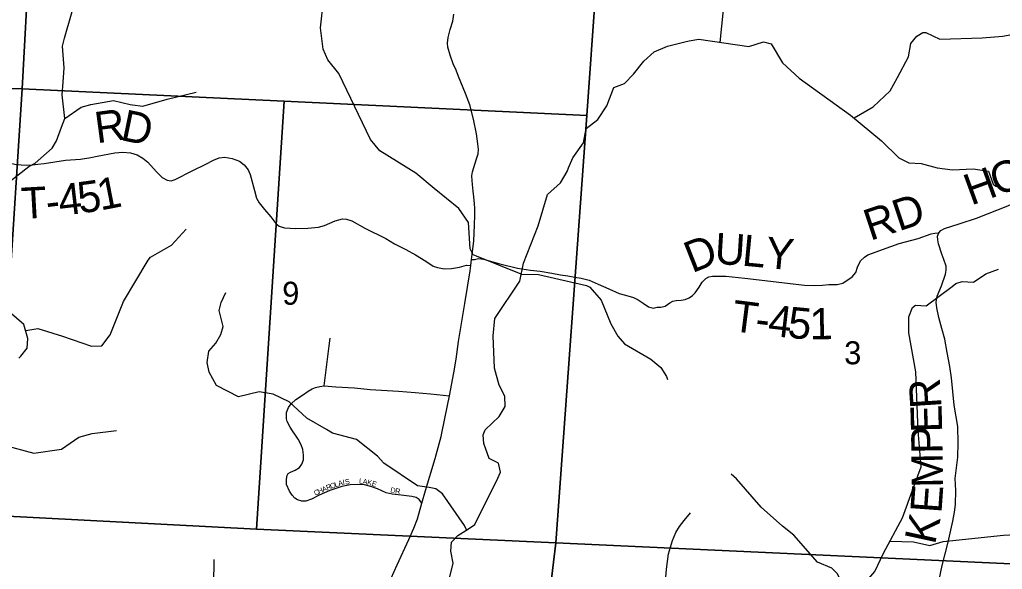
# Model space of a CAD drawing. Extents: x 1878108 to 2183446, y 146837 to 508383.
# Drawn here: x 2036927 to 2046360, y 319271 to 324551 of the extents above; entities that cross this region are included whole.
import ezdxf

# ---------------------------------------------------------------- set-up
doc = ezdxf.new("R2010")
doc.units = 0
for name, color, linetype in [('GM_X_County_Road', 7, 'Continuous'), ('GM_X_County_Road_Text', 7, 'Continuous'), ('GM_X_Minor_River', 7, 'Continuous'), ('GM_X_Section', 7, 'Continuous'), ('GM_X_Section_Text', 7, 'Continuous'), ('GM_X_Township_Road', 7, 'Continuous'), ('GM_X_Township_Road_Text', 7, 'Continuous'), ('GM_X_Township_Subdivision', 7, 'Continuous'), ('GM_X_Township_Subdivision_Text', 7, 'Continuous')]:
    doc.layers.add(name, color=color, linetype=linetype)

msp = doc.modelspace()

# ---------------------------------------------------------------- linework, layer by layer
at = {"layer": 'GM_X_County_Road'}
for points in [[(2041269.8, 322297.9), (2041284.9, 322422.1), (2041293.9, 322578.5), (2041296.1, 322669), (2041296.1, 322736.1), (2041291.9, 322782.5), (2041287.2, 322850.1), (2041280.5, 322903.8), (2041273.8, 322967.5), (2041270.4, 323006.6), (2041268.2, 323049), (2041273.8, 323090.4), (2041284.9, 323131.7), (2041312.9, 323213.3), (2041327.4, 323261.4), (2041330.8, 323306.1), (2041324, 323356.4), (2041310.6, 323452.5), (2041283.8, 323595.6), (2041246.9, 323733), (2041205.6, 323840.3), (2041140.8, 324003.5), (2041116.2, 324065), (2041089.3, 324126.4), (2041058, 324208), (2041036.8, 324287.4), (2041033.5, 324324.3), (2041039, 324377.9), (2041059.2, 324456.1), (2041084.9, 324535.5), (2041094.9, 324603.7)], [(2046142, 322656.2), (2046379.4, 322750), (2046479.7, 322791.1), (2046660.9, 322855.4), (2047032.3, 322992.9), (2047151.9, 323036.6), (2047223.9, 323075.2), (2047316.4, 323151), (2047355.3, 323178.6), (2047429.5, 323215.3), (2047478.4, 323255.1), (2047541.3, 323334.8), (2047615.9, 323427.3), (2047677.6, 323510.9), (2047707.1, 323558.4), (2047747, 323635.6), (2047755, 323655.9)], [(2045752.9, 319171.1), (2045782.1, 319307.1), (2045838.1, 319530.9), (2045885.1, 319733), (2045901.6, 319819.5), (2045910.5, 319893.2), (2045911.8, 320029.2), (2045907.9, 320142.3), (2045930.9, 320349.6), (2045936, 320481.8), (2045932.1, 320644.5), (2045897.8, 320848), (2045871.1, 321111.1), (2045854.6, 321217.9), (2045830.4, 321353.9), (2045807.6, 321481.1), (2045778.3, 321582.8), (2045750.3, 321689.6), (2045731.3, 321783.6), (2045724.9, 321838.3), (2045732.5, 321894.2), (2045774.5, 321994.7), (2045812.6, 322107.3), (2045819, 322143.3), (2045819, 322181.9), (2045797.2, 322246.1), (2045777.9, 322297.5), (2045745.7, 322396.5), (2045739.3, 322435.1), (2045736.7, 322469.8), (2045749.6, 322504.5), (2045770.2, 322526.3), (2045804.9, 322544.3), (2045946.2, 322588), (2046122.3, 322648.4), (2046142, 322656.2)], [(2041250.2, 322138.1), (2041258.7, 322190.3), (2041263.5, 322246.1), (2041269.8, 322297.9)], [(2040436.7, 319059.3), (2040551.8, 319315.4), (2040661.1, 319556.4), (2040712, 319665.5), (2040744.7, 319756.4), (2040787.1, 319905.5), (2040821.1, 320026.7), (2040914.4, 320337), (2040971.4, 320545.5), (2041012.6, 320735.8), (2041052.6, 320938.2), (2041093.8, 321157.6), (2041115.6, 321289.7), (2041139.9, 321458.2), (2041199.3, 321824.3), (2041250.2, 322138.1)]]:
    msp.add_lwpolyline(points, dxfattribs=at)
at = {"layer": 'GM_X_Minor_River'}
for points in [[(2043652.3, 324332.3), (2043682.3, 324645.8), (2043736.7, 324719.9), (2043869.4, 324819.7), (2043901.6, 324871.7), (2044019.1, 325184.5), (2044045.3, 325212.5), (2044131.5, 325222.1), (2044157.7, 325254.1), (2044230, 325316.1), (2044387.2, 325532.2), (2044552, 325654), (2044652.7, 325780.1), (2044719.1, 325844), (2044834.1, 326054.4), (2044902.6, 326140.4), (2044989.6, 326334.8), (2045007.8, 326374.9), (2045034.2, 326463.1), (2045030.7, 326579.6), (2044897.9, 326939.7), (2044840.8, 327154.9), (2044827.5, 327325.6)], [(2037361.7, 323602.4), (2037335.1, 323828.4), (2037345, 323950.6), (2037352.8, 324086.8), (2037338.6, 324297.1), (2037358.5, 324371.2), (2037485.8, 324820.1), (2037541.6, 324932.3), (2037709.4, 325024.8), (2037841.1, 325125.1), (2038039.1, 325301.9)], [(2041741.6, 322105.7), (2041310.5, 322278.9), (2041278.5, 322291.1), (2041252.7, 322349.4), (2041235.7, 322602.6), (2041142.1, 322737.5), (2040906.6, 322929.4), (2040730.9, 323076.8), (2040385.2, 323289.2), (2040295.5, 323400.1), (2039989.7, 324032.1), (2039886.1, 324165.1), (2039840.4, 324265.7), (2039813.3, 324472.7), (2039842.4, 324733.6)], [(2044936, 323607.8), (2045120.7, 323713.4), (2045281.7, 323867.3), (2045352.3, 323993.5), (2045459.3, 324191.8), (2045479.9, 324320.3), (2045538.3, 324392.3), (2045596.5, 324426.2), (2045626.6, 324426), (2045760.5, 324363.2), (2046167.3, 324377.4), (2046363.6, 324390.5), (2046646.3, 324445.5), (2046744.6, 324483.2), (2046835, 324533)], [(2041057.1, 319199.4), (2041087.7, 319329.8), (2041066.2, 319444.3), (2041072.5, 319532.7), (2041132.9, 319594.7), (2041235.3, 319660.5), (2041297.6, 319702.3), (2041517.9, 320147.2), (2041542.1, 320205.3), (2041524.5, 320291.7), (2041432.5, 320334.3), (2041381, 320481.2), (2041377.4, 320563.5), (2041393.6, 320609.6), (2041530.4, 320739.6), (2041586.9, 320833.7), (2041585.3, 320934.1), (2041529.6, 321038.8), (2041484.2, 321203.7), (2041473.5, 321513), (2041488.3, 321679.6), (2041728.2, 322040), (2041762.9, 322210.5), (2041902.7, 322571.4), (2041992.1, 322872.2), (2042116.8, 322982.1), (2042181.3, 323092.3), (2042195.5, 323128.3), (2042238, 323224.5), (2042338.7, 323366.7), (2042363.4, 323505.1), (2042477.9, 323593), (2042564.6, 323723.1), (2042631.5, 323897.5), (2042731.8, 323937.2), (2042818.3, 324027.2), (2042917, 324151.3), (2043017.5, 324241.2), (2043146, 324294.8), (2043310.4, 324338.2), (2043352.5, 324346.1), (2043446.7, 324361.7), (2043925.2, 324293.2), (2044067.7, 324338.8), (2044141.7, 324318.4), (2044249.1, 324137.1), (2044410.7, 323989.8), (2044902, 323632.1), (2045199.5, 323387.7), (2045365.1, 323224.3), (2045463, 323175.6), (2045581.2, 323169.1), (2045733.3, 323126.2), (2045881.5, 323109.5), (2046079.8, 323118.6), (2046226, 323093.8), (2046271.5, 322969.1), (2046297.5, 322950.9), (2046475.5, 322897.9)], [(2036766.7, 322944.1), (2037014.2, 323138.9), (2037076.1, 323171), (2037237.8, 323317.5), (2037281.7, 323385.7), (2037327.5, 323518), (2037361.3, 323602.1), (2037517.1, 323708.6), (2037608.9, 323734.8), (2037826.7, 323773.2), (2037986.5, 323735.5), (2038008.5, 323731.5), (2038108.4, 323719.7), (2038344.1, 323788.2), (2038621.7, 323852.8)], [(2036986.1, 321564.6), (2037101.9, 321584.9), (2037337.7, 321511.2), (2037617.6, 321413.6), (2037715.5, 321417.8), (2037795.3, 321522), (2037924.8, 321842.7), (2038160.1, 322241.7), (2038184, 322269.8), (2038385.7, 322384.3), (2038525.3, 322538.8)], [(2044903.5, 318935), (2044954.6, 318982.7), (2044999.1, 319089), (2045136, 319251), (2045218.9, 319425.3), (2045400.6, 319765.9), (2045508, 320056.6), (2045581, 320255.1), (2045552.4, 320602.7), (2045528.7, 321167.1), (2045462.2, 321542.9), (2045460.8, 321695.6), (2045497.3, 321785.8), (2045527.4, 321807.7), (2045627.5, 321803.2), (2045876.7, 321988.9), (2045912.9, 322016.8), (2045975.1, 322034.6), (2046081.2, 322030.1), (2046201.8, 322109.9), (2046324.2, 322153.5)], [(2041741.5, 322105.6), (2041906.7, 322101.4), (2042367, 321996.9), (2042399, 321982.7), (2042508.7, 321855.7), (2042599.9, 321628.3), (2042669.5, 321509.5), (2042733.3, 321436.9), (2042985.1, 321291.2), (2043082.9, 321208.4), (2043136.6, 321123.8), (2043144.5, 321093.6)], [(2039684.1, 320721.4), (2039512.2, 320880.3), (2039360.3, 320952.1), (2039224.4, 320975.9), (2039028.6, 320927.5), (2038814.8, 321035.2), (2038746.7, 321165.3), (2038726.6, 321257.4), (2038742.5, 321365.6), (2038810.3, 321441.8), (2038858.1, 321526), (2038880, 321602.1), (2038841.9, 321758.3), (2038859.8, 321832.4), (2038905.6, 321930.6)], [(2036918.4, 321298.1), (2036938.4, 321318.2), (2036998.2, 321394.4), (2037006.1, 321486.6), (2036968, 321622.7), (2036826, 321744.6)], [(2041214.5, 319650.1), (2041195.4, 319692.8), (2040984.4, 319997), (2040922.4, 320043.5), (2040856.4, 320057.8), (2040744.3, 320072.4), (2040422.7, 320290.8), (2040360.8, 320357.3), (2040159.2, 320518.9), (2039929.1, 320580.2), (2039871.1, 320612.6), (2039683.3, 320721.9)], [(2036407.8, 320580.2), (2036776.9, 320462.1), (2037063.5, 320386.5), (2037327.8, 320425.2), (2037495.8, 320540), (2037623.9, 320574.4), (2037856.2, 320605.1)], [(2045281.3, 319542.2), (2045505.8, 319534.5), (2045663.9, 319501.6), (2045792.3, 319537.2), (2046371.5, 319598.8), (2046545.8, 319608), (2046660.1, 319627.6), (2046718.4, 319671.5), (2046730.7, 319737.7), (2046715.1, 319852.3), (2046701.5, 319954.8), (2046710, 320057.1), (2046823.3, 320321.7), (2046837.7, 320416), (2046834, 320486.3)], [(2044943.9, 318818.1), (2044864.7, 319047.4), (2044777.3, 319228.5), (2044721.5, 319283), (2044585.5, 319339.9), (2044358.2, 319598), (2044248.4, 319684.8), (2044044.8, 319868.5), (2043807.6, 320140.7), (2043755.7, 320185.1)], [(2038790.7, 319364.9), (2038786.9, 319126.5), (2038807, 319070.5), (2038853.1, 318966.4), (2038981, 318817.8)]]:
    msp.add_lwpolyline(points, dxfattribs=at)
at = {"layer": 'GM_X_Section'}
for points in [[(2036950.3, 323885.9), (2036627, 323893.3), (2036446.5, 321096.2), (2033640.2, 321275.3), (2033930.4, 325304), (2037017.7, 325125.7)], [(2037017.7, 325125.7), (2042458, 324849.1), (2042369.9, 323629.5), (2039466.2, 323766.9), (2036950.3, 323885.9)], [(2042458, 324849.1), (2042459.2, 324865.4), (2047851.5, 324568.1), (2047485.7, 319275.5), (2042073.5, 319526.8), (2042369.9, 323629.5)], [(2036950.3, 323885.9), (2036684.8, 319786.8), (2036363.4, 319807.6), (2036446.5, 321096.2), (2036627, 323893.3)], [(2039466.2, 323766.9), (2039201.1, 319655.3), (2036684.8, 319786.8), (2036950.3, 323885.9)], [(2042369.9, 323629.5), (2042073.5, 319526.8), (2039201.1, 319655.3), (2039466.2, 323766.9)], [(2039201.1, 319655.3), (2042073.5, 319526.8), (2041944.4, 318463.8), (2041709.1, 314235.9), (2036314.8, 314510.5), (2036455.6, 316598.4), (2036600.2, 318782.6), (2036684.8, 319786.8)], [(2047485.7, 319275.5), (2047167.4, 313959), (2041709.1, 314235.9), (2041944.4, 318463.8), (2042073.5, 319526.8)]]:
    msp.add_lwpolyline(points, close=True, dxfattribs=at)
at = {"layer": 'GM_X_Township_Road'}
for points in [[(2035221.6, 323292.9), (2035423.7, 323292.9), (2035721.8, 323286.1), (2035830.9, 323271.5), (2036124.9, 323239.9), (2036573.9, 323218.2), (2036686.6, 323203.7), (2036782.4, 323184.3), (2036879.3, 323163.7), (2036942.4, 323155.2), (2037024.8, 323154), (2037101.4, 323162.8)], [(2037101.4, 323162.8), (2037161.8, 323169.7), (2037366.6, 323200), (2037510.8, 323210.9), (2037611.2, 323225.8), (2037672, 323240), (2037841.7, 323272.7), (2037918.1, 323277.6), (2037990.8, 323271.5), (2038053.9, 323253.3), (2038109.6, 323220.6), (2038156.9, 323180.6), (2038241.7, 323088.5), (2038295.1, 323034), (2038341.1, 323009.7), (2038381.1, 323003.7), (2038419.9, 323015.8), (2038583.5, 323097), (2038714.5, 323163.7), (2038788.4, 323201.2), (2038841.7, 323223), (2038897.5, 323230.3), (2038967.8, 323217), (2039036.9, 323190.3), (2039081.7, 323155.2), (2039119.3, 323107.9), (2039138.7, 323064.3), (2039182.3, 322909.1), (2039201.7, 322836.4), (2039224.7, 322791.5), (2039278.1, 322726.1), (2039337.5, 322657), (2039387.2, 322594), (2039416.3, 322568.5), (2039468.4, 322550.3), (2039576.3, 322543.1), (2039693.8, 322547.9), (2039794.4, 322558.8), (2039853.1, 322574.8), (2039954.4, 322618.2), (2040025.9, 322637.6), (2040063.5, 322634), (2040116.9, 322618.2), (2040239.3, 322549.1), (2040441.7, 322447.3), (2040524.1, 322396.4), (2040633.2, 322341.8), (2040726.5, 322292.2), (2040825.9, 322230.3), (2040895, 322181.9), (2040936.2, 322169.7), (2041000.5, 322158.8), (2041070.8, 322161.2), (2041148.4, 322172.2), (2041215, 322191.5), (2041258.7, 322190.3)], [(2041263.5, 322246.1), (2041293.4, 322247.4), (2041331.9, 322256.4), (2041378.2, 322248.7), (2041536.3, 322203.7), (2041704.7, 322165.1), (2041830.6, 322145.9), (2041921.9, 322134.3), (2042033.7, 322116.3), (2042117.3, 322099.6), (2042189.2, 322089.3), (2042254.8, 322077.7), (2042315.2, 322066.2), (2042393.6, 322046.9), (2042478.4, 322010.9), (2042583.8, 321964.6), (2042681.5, 321920.9), (2042743.2, 321905.5), (2042819.1, 321882.4), (2042865.3, 321860.5), (2042912.9, 321827.1), (2042964.3, 321793.7), (2043006.7, 321779.6), (2043045.3, 321788.5), (2043080, 321788.5), (2043122.4, 321800.1), (2043168.7, 321829.7), (2043195.7, 321847.7), (2043227.8, 321854.1), (2043277.9, 321856.7), (2043315.2, 321863.1), (2043352.5, 321878.5), (2043384.6, 321900.4), (2043410.3, 321926.2), (2043450.1, 321980.1), (2043479.7, 322027.6), (2043513.1, 322064.9), (2043541.4, 322080.3), (2043576.1, 322086.7), (2043621.1, 322088), (2043704.2, 322085.4), (2043888.4, 322068.7), (2044461.7, 322000.6), (2044555.5, 321998.1), (2044632.6, 322001.9), (2044693.1, 322005.8), (2044772.7, 322007.1), (2044828, 322018.6), (2044918, 322080.3), (2044954, 322121.4), (2044970.7, 322172.9), (2044997.7, 322234.6), (2045036.2, 322269.3), (2045069.7, 322291.1), (2045288.2, 322370.8), (2045369.1, 322399.1), (2045552.9, 322449.2), (2045677.6, 322492.9), (2045712.3, 322500.6), (2045749.6, 322504.5)], [(2039849, 321032.8), (2039897.9, 321419.1), (2039907.2, 321492.2)], [(2042586.3, 318189.9), (2042662, 318246.6), (2042785.6, 318362.7), (2042892.9, 318472.5), (2043026.6, 318616.3), (2043097.1, 318683.5), (2043161.3, 318752.7), (2043186.9, 318793.8), (2043195.9, 318838.6), (2043186.9, 318881), (2043160, 318946.3), (2043147.1, 318993.8), (2043143.3, 319029.7), (2043139.5, 319086.1), (2043127.9, 319192.5), (2043134.3, 319272), (2043144.6, 319345.1), (2043154.5, 319420.8), (2043193.3, 319549), (2043225.4, 319623.3), (2043260, 319681), (2043306.1, 319740), (2043366.4, 319813.1)]]:
    msp.add_lwpolyline(points, dxfattribs=at)
at = {"layer": 'GM_X_Township_Subdivision'}
msp.add_lwpolyline([(2040787.1, 319905.5), (2040760.5, 319943.1), (2040731.4, 319960.1), (2040692.6, 319971), (2040589.6, 319983.1), (2040501.1, 319994), (2040445.3, 320007.3), (2040362.9, 320043.7), (2040297.5, 320067.9), (2040235.6, 320082.5), (2040171.4, 320087.3), (2040098.7, 320083.7), (2040018.7, 320067.9), (2039903.5, 320027.9), (2039800.5, 319983.1), (2039727.8, 319944.3), (2039674.4, 319927.3), (2039635.6, 319926.1), (2039594.4, 319938.3), (2039569, 319955.2), (2039542.3, 319984.3), (2039516.9, 320021.9), (2039489, 320087.3), (2039486.6, 320124.9), (2039491.4, 320167.3), (2039504.7, 320192.8), (2039525.3, 320203.7), (2039570.2, 320223.1), (2039612.6, 320249.8), (2039636.9, 320280.1), (2039652.6, 320321.3), (2039652.6, 320369.8), (2039644.1, 320423.1), (2039628.4, 320467.9), (2039599.3, 320522.5), (2039575, 320558.8), (2039546, 320600.1), (2039522.9, 320635.2), (2039493.8, 320689.8), (2039486.6, 320717.6), (2039489, 320775.8), (2039507.2, 320826.7), (2039531.4, 320861.9), (2039576.3, 320900.7), (2039640.5, 320944.3), (2039695, 320981.9), (2039733.8, 321003.7), (2039766.6, 321018.2), (2039806.6, 321026.7), (2039849, 321032.8), (2039961.7, 321025.5), (2040141.1, 321013.4), (2040292.6, 320998.8), (2040561.7, 320981.9), (2040721.7, 320971), (2040872, 320957.6), (2041052.6, 320938.2)], dxfattribs=at)

# ---------------------------------------------------------------- texts
at = {"layer": 'GM_X_County_Road_Text'}
for s, rotation, p in [('O', 19.9971, (2046307.9, 322853.6)), ('H', 19.99835, (2046059.9, 322763.3)), ('R', 93.7326, (2045776.7, 320825)), ('E', 91.50747, (2045783.1, 320588.2)), ('P', 90.81731, (2045786.1, 320381.9)), ('M', 90.93054, (2045791.4, 320056.5)), ('E', 85.87693, (2045774.5, 319804.3)), ('K', 77.75843, (2045712, 319501.2))]:
    msp.add_text(s, height=300, rotation=rotation, dxfattribs=at).set_placement(p)
at = {"layer": 'GM_X_Section_Text'}
for s, p in [('9', (2039447.2, 321812.2)), ('3', (2044841.6, 321240.3))]:
    msp.add_text(s, height=221, rotation=0.00001, dxfattribs=at).set_placement(p)
at = {"layer": 'GM_X_Township_Road_Text'}
for s, rotation, p in [('R', 7.68079, (2037667.9, 323362.1)), ('D', 348.3543, (2037885.4, 323395.9)), ('5', 8.0493, (2037504.1, 322688)), ('1', 11.06738, (2037702.7, 322716.5)), ('T', 3.19968, (2036949.1, 322636.3)), ('4', 6.7801, (2037314.9, 322665.4)), ('RD', 18.43495, (2045091.5, 322424.5)), ('-', 6.911, (2037193.9, 322650.7)), ('D', 21.53286, (2043381.1, 322114)), ('U', 356.40958, (2043592.6, 322205.5)), ('L', 354.54057, (2043853.5, 322189.2)), ('Y', 354.5203, (2044076.8, 322167.8)), ('T', 352.82023, (2043752.6, 321561)), ('4', 353.49292, (2044101.4, 321518.5)), ('5', 354.56008, (2044291.1, 321496.9)), ('1', 1.18646, (2044512.8, 321478)), ('-', 353.46113, (2043978.8, 321532.5))]:
    msp.add_text(s, height=300, rotation=rotation, dxfattribs=at).set_placement(p)
at = {"layer": 'GM_X_Township_Subdivision_Text'}
for s, rotation, p in [('A', 24.25764, (2039840.7, 320011.2)), ('R', 22.08554, (2039880.4, 320029.1)), ('O', 19.19516, (2039916.4, 320043.8)), ('L', 18.89289, (2039957.9, 320058.2)), ('A', 15.44105, (2039990.5, 320069.4)), ('I', 10.15234, (2040031.7, 320080.8)), ('S', 9.55216, (2040053.2, 320084.7)), ('L', 354.47158, (2040182.6, 320096.5)), ('A', 351.44329, (2040216.9, 320093.2)), ('K', 346.47792, (2040259.3, 320086.9)), ('E', 339.69015, (2040300.6, 320077)), ('C', 24.251, (2039764.5, 319976.9)), ('H', 24.25884, (2039800.6, 319993.2)), ('D', 346.76949, (2040480.9, 320012.1)), ('R', 351.94691, (2040528.5, 320001.1))]:
    msp.add_text(s, height=50, rotation=rotation, dxfattribs=at).set_placement(p)

doc.saveas('drawing.dxf')
